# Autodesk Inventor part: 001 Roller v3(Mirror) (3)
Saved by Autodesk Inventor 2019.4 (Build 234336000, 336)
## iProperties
Created: 2020-06
Part Number: 001 Roller v3(Mirror) (3)
Material: Generic
Document SubType Name: Modeling
Designer: Administrator
Density: 1 g/cm^3
Appearance: Default
Title: 001 Roller v3(Mirror) (3)
Author: Administrator
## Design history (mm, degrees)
